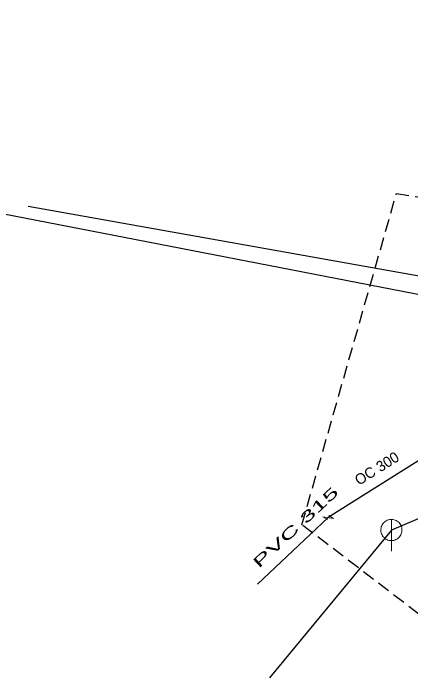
# Model space of a CAD drawing. Extents: x -725643 to -725418, y -978375 to -978221.
# Drawn here: x -725594.1 to -725556.5, y -978374.7 to -978311.9 of the extents above; entities that cross this region are included whole.
import ezdxf

# ---------------------------------------------------------------- set-up
doc = ezdxf.new("R2010")
doc.units = 0
doc.header["$LTSCALE"] = 0.4
doc.linetypes.add('MEDIUM_DASHED', pattern=[4.5, 3, -1.5])
doc.layers.add('1', color=7, linetype='Continuous')
for name, color, linetype, lineweight in [('14', 7, 'Continuous', 25), ('17', 7, 'Continuous', 25), ('22', 7, 'Continuous', 13), ('47', 7, 'Continuous', 13), ('63', 7, 'MEDIUM_DASHED', 25)]:
    doc.layers.add(name, color=color, linetype=linetype, lineweight=lineweight)

msp = doc.modelspace()

# ---------------------------------------------------------------- linework, layer by layer
at = {"layer": '14'}
for p, q in [((-725535.414, -978351.036), (-725558.362, -978360.71)), ((-725558.362, -978360.71), (-725569.885, -978374.657))]:
    msp.add_line(p, q, dxfattribs=at)
msp.add_lwpolyline([(-725527.513, -978334.331), (-725528.055, -978335.436), (-725528.703, -978336.338), (-725529.951, -978337.403), (-725531.603, -978338.206), (-725534.392, -978338.607), (-725536.813, -978338.747), (-725553.081, -978337.228), (-725592.702, -978330.168)], dxfattribs=at)
at = {"layer": '17'}
for p, q in [((-725552.39, -978352.015), (-725564.342, -978359.539)), ((-725564.342, -978359.539), (-725571.012, -978365.831))]:
    msp.add_line(p, q, dxfattribs=at)
msp.add_lwpolyline([(-725642.709, -978318.689), (-725622.261, -978324.109), (-725596.17, -978330.625), (-725550.989, -978339.387)], dxfattribs=at)
at = {"layer": '22'}
msp.add_line((-725558.362, -978362.71), (-725558.361, -978359.71), dxfattribs=at)
msp.add_lwpolyline([(-725557.362, -978360.71), (-725557.367, -978360.601), (-725557.385, -978360.493), (-725557.415, -978360.387), (-725557.455, -978360.286), (-725557.507, -978360.189), (-725557.569, -978360.099), (-725557.641, -978360.016), (-725557.721, -978359.942), (-725557.809, -978359.876), (-725557.903, -978359.821), (-725558.003, -978359.776), (-725558.108, -978359.743), (-725558.215, -978359.721), (-725558.324, -978359.711), (-725558.434, -978359.713), (-725558.542, -978359.727), (-725558.649, -978359.752), (-725558.752, -978359.789), (-725558.85, -978359.838), (-725558.942, -978359.896), (-725559.028, -978359.965), (-725559.105, -978360.042), (-725559.174, -978360.128), (-725559.233, -978360.22), (-725559.281, -978360.318), (-725559.318, -978360.421), (-725559.344, -978360.528), (-725559.358, -978360.636), (-725559.361, -978360.746), (-725559.351, -978360.855), (-725559.33, -978360.962), (-725559.296, -978361.066), (-725559.252, -978361.166), (-725559.197, -978361.261), (-725559.131, -978361.349), (-725559.057, -978361.429), (-725558.974, -978361.501), (-725558.884, -978361.563), (-725558.788, -978361.615), (-725558.686, -978361.656), (-725558.581, -978361.686), (-725558.473, -978361.704), (-725558.363, -978361.71), (-725558.254, -978361.704), (-725558.146, -978361.686), (-725558.041, -978361.657), (-725557.939, -978361.616), (-725557.842, -978361.564), (-725557.752, -978361.502), (-725557.669, -978361.431), (-725557.594, -978361.351), (-725557.529, -978361.263), (-725557.473, -978361.169), (-725557.429, -978361.069), (-725557.395, -978360.965), (-725557.373, -978360.857), (-725557.363, -978360.748)], close=True, dxfattribs=at)
at = {"layer": '47'}
msp.add_line((-725564.844, -978359.455), (-725564.412, -978359.727), dxfattribs=at)
msp.add_lwpolyline([(-725564.844, -978359.455), (-725563.839, -978359.622), (-725564.271, -978359.35)], dxfattribs=at)
at = {"layer": '63'}
msp.add_lwpolyline([(-725440.663, -978348.762), (-725504.582, -978352.39), (-725504.582, -978352.39), (-725528.587, -978359.368), (-725528.587, -978359.368), (-725551.474, -978371.929), (-725551.474, -978371.929), (-725566.826, -978360.206), (-725566.826, -978360.206), (-725557.894, -978328.944), (-725533.89, -978332.573), (-725533.89, -978332.573), (-725529.424, -978311.918), (-725529.424, -978311.918), (-725514.351, -978316.105), (-725514.351, -978316.105), (-725517.422, -978329.502), (-725517.422, -978329.502), (-725504.582, -978332.573), (-725504.582, -978332.573), (-725495.092, -978321.408)], dxfattribs=at)

# ---------------------------------------------------------------- texts
at = {"layer": '1'}
msp.add_text('OC 300', height=1, rotation=32, dxfattribs=at).set_placement((-725561.429, -978356.541))
at = {"layer": '1', "width": 1.95}
msp.add_text('PVC 315 ', height=1, rotation=43, dxfattribs=at).set_placement((-725570.898, -978364.369))

doc.saveas('drawing.dxf')
